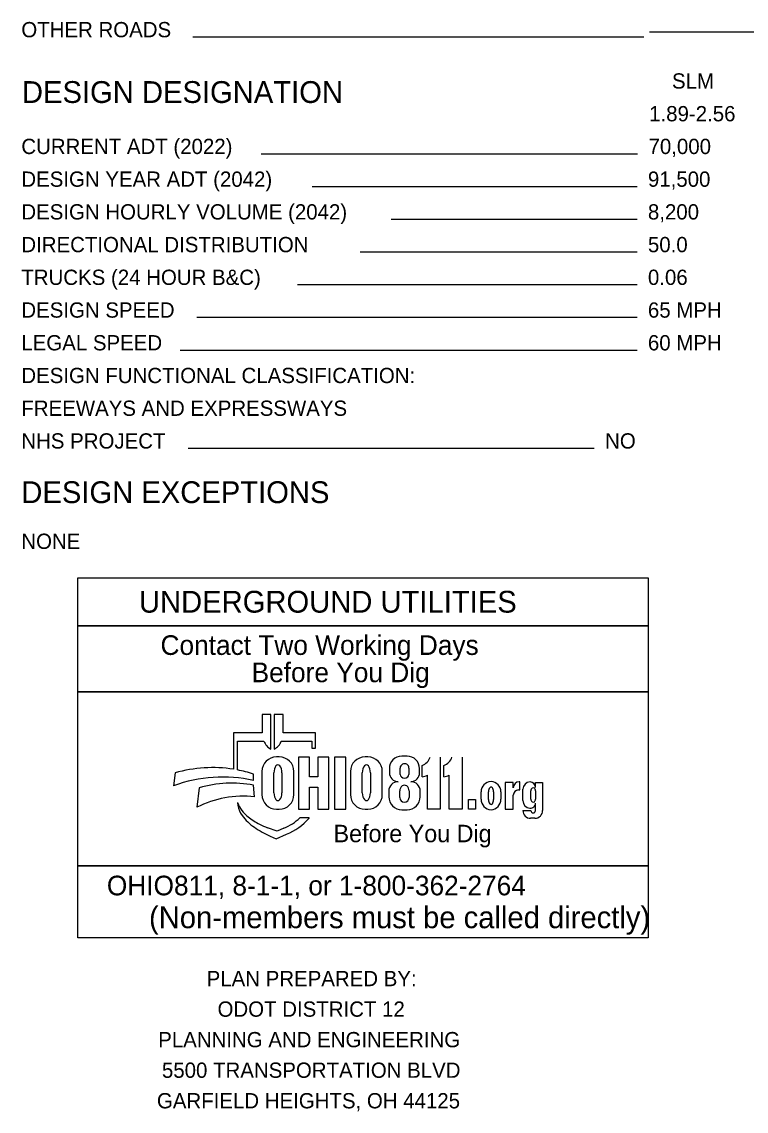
# Model space of a CAD drawing. Extents: x -17.5 to 72.9, y -57.8 to 32.3.
# Drawn here: x 1.44 to 8.08, y -47.89 to -37.91 of the extents above; entities that cross this region are included whole.
import ezdxf

# ---------------------------------------------------------------- set-up
doc = ezdxf.new("R2010")
doc.units = 0
doc.layers.add('SH_Data', color=7, linetype='Continuous')

msp = doc.modelspace()

# ---------------------------------------------------------------- linework, layer by layer
at = {"layer": 'SH_Data'}
for p, q in [((7.1453, -38.0478), (3.011, -38.0478)), ((8.4453, -38.0022), (7.1953, -38.0022)), ((7.0877, -39.1182), (3.6388, -39.1182)), ((7.0821, -39.4182), (4.1045, -39.4182)), ((7.0821, -39.7182), (4.8305, -39.7182)), ((7.0821, -40.0182), (4.544, -40.0182)), ((7.0821, -40.3182), (3.9711, -40.3182)), ((7.0821, -40.6182), (3.0488, -40.6182)), ((7.0821, -40.9182), (2.8941, -40.9182)), ((6.6897, -41.8182), (2.9695, -41.8182)), ((3.7267, -44.257), (3.6466, -44.257)), ((3.6466, -44.257), (3.6466, -44.4236)), ((3.7267, -44.5738), (3.7267, -44.257)), ((3.8379, -44.257), (3.7578, -44.257)), ((3.7578, -44.257), (3.7578, -44.5738)), ((3.8379, -44.4236), (3.8379, -44.257)), ((3.6466, -44.4236), (3.3837, -44.4236)), ((3.3837, -44.4236), (3.3837, -44.758)), ((4.1356, -44.4236), (3.8379, -44.4236)), ((4.1356, -44.5637), (4.1356, -44.4236)), ((3.4215, -44.7646), (3.4215, -44.5004)), ((3.4215, -44.5004), (3.6622, -44.5004)), ((3.8224, -44.5004), (4.1008, -44.5004)), ((4.1008, -44.5004), (4.1008, -44.5637)), ((4.1008, -44.5637), (4.1356, -44.5637)), ((4.9753, -44.6383), (4.9264, -44.6383)), ((3.8034, -44.6448), (3.7787, -44.6448)), ((4.0813, -44.6463), (3.9798, -44.6463)), ((3.9798, -44.6463), (3.9798, -45.1243)), ((4.6142, -44.6448), (4.5895, -44.6448)), ((5.1123, -44.8266), (5.1123, -44.7247)), ((5.279, -44.6463), (5.279, -45.1243)), ((5.3124, -44.8266), (5.3124, -44.7247)), ((5.4791, -44.6463), (5.4791, -45.1243)), ((2.8487, -44.7922), (2.8346, -44.909)), ((3.5676, -44.8599), (3.5676, -44.8019)), ((3.6451, -44.7785), (3.6451, -44.9906)), ((3.754, -44.9736), (3.754, -44.7908)), ((3.8284, -44.7908), (3.8284, -44.9736)), ((3.9371, -44.9906), (3.9371, -44.7785)), ((4.4558, -44.7785), (4.4558, -44.9906)), ((4.5647, -44.9736), (4.5647, -44.7908)), ((4.6391, -44.7908), (4.6391, -44.9736)), ((4.7478, -44.9906), (4.7478, -44.7785)), ((4.8124, -44.7523), (4.8124, -44.7886)), ((4.9112, -44.8056), (4.9112, -44.7469)), ((4.9921, -44.7469), (4.9921, -44.8056)), ((5.0893, -44.7886), (5.0893, -44.7523)), ((5.1606, -45.1243), (5.1606, -44.8126)), ((5.3607, -45.1243), (5.3607, -44.8126)), ((3.0693, -44.9275), (3.0474, -45.1069)), ((3.5777, -45.0104), (3.5684, -44.9044)), ((4.0813, -45.1243), (4.0813, -44.9222)), ((5.9479, -44.8808), (5.8749, -44.8808)), ((5.8749, -44.8808), (5.8749, -45.1243)), ((5.9479, -44.9279), (5.9479, -44.8808)), ((6.0086, -44.8731), (6.0027, -44.8731)), ((6.0086, -44.9476), (6.0086, -44.8731)), ((6.0369, -45.046), (6.0369, -44.942)), ((6.1518, -44.9258), (6.1518, -44.8795)), ((6.1518, -44.8795), (6.2169, -44.8795)), ((6.2169, -44.8795), (6.2169, -45.1377)), ((4.8069, -44.9587), (4.8069, -45.0095)), ((4.9077, -45.0184), (4.9077, -44.9573)), ((4.9926, -44.9573), (4.9926, -45.0184)), ((5.0953, -45.0095), (5.0953, -44.9587)), ((5.6529, -45.0334), (5.6529, -44.9656)), ((5.7202, -45.0346), (5.7202, -44.9656)), ((5.7682, -44.9656), (5.7682, -45.0346)), ((5.8354, -44.9656), (5.8354, -45.0334)), ((5.9479, -45.1243), (5.9479, -44.9969)), ((5.9971, -44.9476), (6.0086, -44.9476)), ((6.1091, -45.0321), (6.1091, -44.9558)), ((6.1518, -44.9558), (6.1518, -45.0321)), ((3.4205, -45.0641), (3.425, -45.0909)), ((3.7787, -45.1243), (3.8034, -45.1243)), ((3.9798, -45.1243), (4.0813, -45.1243)), ((4.5895, -45.1243), (4.6142, -45.1243)), ((4.9278, -45.1305), (4.9744, -45.1305)), ((5.279, -45.1243), (5.1606, -45.1243)), ((5.4791, -45.1243), (5.3607, -45.1243)), ((5.8749, -45.1243), (5.9479, -45.1243)), ((6.0369, -45.1377), (6.1091, -45.1377)), ((6.1518, -45.1377), (6.1518, -45.0684)), ((4.0789, -45.2043), (3.9931, -45.2043)), ((4.0765, -45.2069), (4.0789, -45.2043)), ((6.147, -45.2076), (6.1067, -45.2076)), ((3.7855, -45.325), (3.6967, -45.2944)), ((3.8468, -45.2984), (3.7855, -45.325)), ((3.7207, -45.3707), (3.7765, -45.3953)), ((3.7765, -45.3953), (3.871, -45.3543)), ((7.1828, -46.3025), (1.9578, -46.3025))]:
    msp.add_line(p, q, dxfattribs=at)
for points in [[(1.9578, -43.0025), (7.1828, -43.0025), (7.1828, -43.4425), (1.9578, -43.4425)], [(1.9578, -43.4425), (7.1828, -43.4425), (7.1828, -44.0475), (1.9578, -44.0475)], [(1.9578, -44.0475), (7.1828, -44.0475), (7.1828, -45.6425), (1.9578, -45.6425)], [(5.5372, -45.0346), (5.603, -45.0346), (5.603, -45.1243), (5.5372, -45.1243)], [(1.9578, -45.6425), (7.1828, -45.6425), (7.1828, -46.3025), (1.9578, -46.3025)]]:
    msp.add_lwpolyline(points, close=True, dxfattribs=at)
for points in [[(4.0813, -44.9222), (4.1575, -44.9222), (4.1575, -45.1243), (4.259, -45.1243), (4.259, -44.6463), (4.1575, -44.6463), (4.1575, -44.8266), (4.0813, -44.8266), (4.0813, -44.6463)], [(4.3097, -45.1243), (4.4125, -45.1243), (4.4125, -44.6463), (4.3097, -44.6463), (4.3097, -45.1243)], [(4.8933, -44.8722), (4.8933, -44.8722)], [(5.0089, -44.8722), (5.0089, -44.8722)]]:
    msp.add_lwpolyline(points, dxfattribs=at)
for centre, radius, start, end in [((3.7986, -44.4455), 0.1471, 201.92963, 240.74693), ((3.6859, -44.4455), 0.1471, 299.25307, 338.07037), ((4.9264, -44.7523), 0.114, 90, 180), ((4.9753, -44.7523), 0.114, 0, 90), ((3.1924, -45.9665), 1.2235, 81.00071, 106.31438), ((3.7787, -44.7785), 0.1337, 90, 180), ((3.8034, -44.7785), 0.1337, 0, 90), ((4.5895, -44.7785), 0.1337, 90, 180), ((4.6142, -44.7785), 0.1337, 0, 90), ((5.0616, -44.6027), 0.1322, 292.55722, 340.73552), ((5.2617, -44.6027), 0.1322, 292.55722, 340.73552), ((3.2866, -46.1624), 1.3324, 77.82382, 109.82736), ((3.1924, -45.9665), 1.2235, 72.14025, 79.20744), ((4.8961, -44.7886), 0.0837, 180, 268.14422), ((5.0056, -44.7886), 0.0837, 272.20579, 0), ((5.1004, -44.695), 0.1322, 275.17327, 297.09312), ((5.3005, -44.695), 0.1322, 275.17327, 297.09312), ((3.368, -45.9797), 1.0937, 79.44002, 105.84672), ((4.8933, -44.9587), 0.0865, 90, 180), ((5.0089, -44.9587), 0.0865, 0, 90), ((5.7485, -44.9656), 0.0956, 92.58863, 180), ((5.7398, -44.9656), 0.0956, 0, 87.41137), ((6.0027, -44.9279), 0.0548, 90, 180), ((6.1054, -44.942), 0.0686, 92.68649, 180), ((6.0994, -44.9258), 0.0524, 0, 86.92624), ((3.4756, -45.9546), 0.9496, 83.82483, 116.80206), ((3.7787, -44.9906), 0.1337, 180, 270), ((3.8034, -44.9906), 0.1337, 270, 0), ((4.5895, -44.9906), 0.1337, 180, 270), ((4.6142, -44.9906), 0.1337, 270, 0), ((4.9278, -45.0095), 0.1209, 180, 270), ((4.9744, -45.0095), 0.1209, 270, 0), ((5.7485, -45.0334), 0.0956, 180, 267.41137), ((5.7398, -45.0334), 0.0956, 272.58863, 0), ((5.9971, -44.9969), 0.0493, 90, 180), ((3.7004, -44.9564), 0.2999, 201.04565, 232.53137), ((3.6361, -45.0549), 0.2141, 189.68174, 216.08842), ((6.106, -45.046), 0.0692, 180, 265.71324), ((6.1067, -45.1377), 0.0699, 180, 270), ((6.1051, -45.0684), 0.0467, 264.78254, 0), ((6.147, -45.1377), 0.0699, 270, 0), ((3.8358, -44.9093), 0.4612, 216.08842, 235.7167), ((3.988, -44.5811), 0.7728, 232.53137, 241.79401), ((3.6326, -44.8048), 0.5381, 293.45821, 312.07118), ((3.6326, -44.8048), 0.599, 293.45821, 317.82862), ((4.0845, -44.5445), 0.9028, 235.7167, 246.23245), ((3.8608, -44.8184), 0.5035, 241.79401, 250.98207)]:
    msp.add_arc(centre, radius, start, end, dxfattribs=at)
for centre, major_axis, ratio, start_param, end_param in [((3.7912, -44.7908), (0, 0.0723), 0.514403, 4.712389, 7.853982), ((4.6019, -44.7908), (0, 0.0723), 0.514403, 4.712389, 7.853982), ((4.9517, -44.7469), (0.0404, 0), 0.969373, 0, 3.141593), ((4.9517, -44.8056), (0.0404, 0), 0.818453, 3.141593, 6.283185), ((4.9502, -44.9573), (0, 0.0535), 0.794529, 4.712389, 7.853982), ((5.7442, -44.9656), (0, 0.0434), 0.553236, 4.712389, 7.853982), ((6.1304, -44.9558), (0, 0.0275), 0.777179, 4.712389, 7.853982), ((3.7912, -44.9736), (0, 0.0723), 0.514403, 1.570796, 4.712389), ((4.6019, -44.9736), (0, 0.0723), 0.514403, 1.570796, 4.712389), ((4.9502, -45.0184), (0.0425, 0), 0.959837, 3.141593, 6.283185), ((5.7442, -45.0346), (0, 0.046), 0.522014, 1.570796, 4.712389), ((6.1304, -45.0321), (0, 0.0275), 0.777179, 1.570796, 4.712389), ((6.1304, -45.1377), (0.0214, 0), 0.959012, 3.141593, 6.283185)]:
    msp.add_ellipse(centre, major_axis=major_axis, ratio=ratio, start_param=start_param, end_param=end_param, dxfattribs=at)

# ---------------------------------------------------------------- texts
for s, height, p in [('OTHER ROADS', 0.14, (1.4397, -38.0478)), ('DESIGN DESIGNATION', 0.2, (1.4453, -38.6498)), ('SLM', 0.14, (7.4025, -38.5182)), ('1.89-2.56', 0.14, (7.1933, -38.8182)), ('CURRENT ADT (2022)', 0.14, (1.4397, -39.1182)), ('70,000', 0.14, (7.1877, -39.1182)), ('DESIGN YEAR ADT (2042)', 0.14, (1.4397, -39.4182)), ('91,500', 0.14, (7.1821, -39.4182)), ('DESIGN HOURLY VOLUME (2042)', 0.14, (1.4397, -39.7182)), ('8,200', 0.14, (7.1821, -39.7182)), ('DIRECTIONAL DISTRIBUTION', 0.14, (1.4397, -40.0182)), ('50.0', 0.14, (7.1821, -40.0182)), ('TRUCKS (24 HOUR B&C)', 0.14, (1.4397, -40.3182)), ('0.06', 0.14, (7.1821, -40.3182)), ('DESIGN SPEED', 0.14, (1.4397, -40.6182)), ('65 MPH', 0.14, (7.1821, -40.6182)), ('LEGAL SPEED', 0.14, (1.4397, -40.9182)), ('60 MPH', 0.14, (7.1821, -40.9182)), ('DESIGN FUNCTIONAL CLASSIFICATION:', 0.14, (1.4397, -41.2182)), ('FREEWAYS AND EXPRESSWAYS', 0.14, (1.4397, -41.5182)), ('NHS PROJECT', 0.14, (1.4397, -41.8182)), ('NO', 0.14, (6.7897, -41.8182)), ('DESIGN EXCEPTIONS', 0.2, (1.4397, -42.3182)), ('NONE', 0.14, (1.4397, -42.7382)), ('UNDERGROUND UTILITIES', 0.2, (2.5175, -43.3225)), ('Contact Two Working Days', 0.18, (2.7151, -43.71)), ('Before You Dig', 0.18, (3.5499, -43.96)), ('Before You Dig', 0.15972, (4.3012, -45.4272)), ('OHIO811, 8-1-1, or 1-800-362-2764', 0.18, (2.2236, -45.9139)), ('(Non-members must be called directly)', 0.2, (2.6099, -46.2154)), ('PLAN PREPARED BY:', 0.14, (3.1378, -46.747)), ('ODOT DISTRICT 12', 0.14, (3.2378, -47.027)), ('PLANNING AND ENGINEERING', 0.14, (2.6941, -47.307)), ('5500 TRANSPORTATION BLVD', 0.14, (2.7282, -47.587)), ('GARFIELD HEIGHTS, OH 44125', 0.14, (2.6823, -47.867))]:
    msp.add_text(s, height=height, dxfattribs=at).set_placement(p)

doc.saveas('drawing.dxf')
